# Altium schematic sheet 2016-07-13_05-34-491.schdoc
size 229 x 134 mm; SheetNumber: 1; SheetTotal: 1
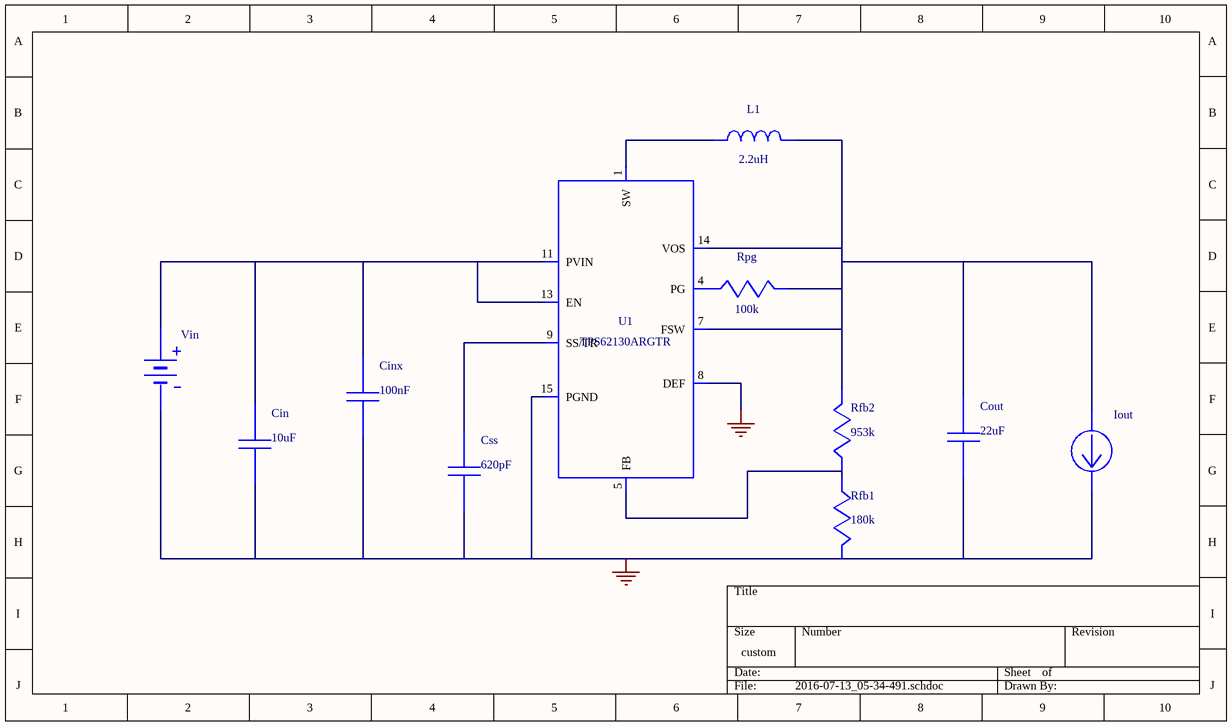
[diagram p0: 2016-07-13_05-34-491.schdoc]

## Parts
Cin  value 10uF  (hidden comment: TMK316BJ106KL-T)
Cinx  value 100nF  (hidden comment: C0603C104K3RACTU)
Cout  value 22uF  (hidden comment: GRM31CR61A226KE19L)
Css  value 620pF  (hidden comment: CL21C621JBCNNNC)
Iout  WB_CURRENT_LOAD  (value not drawn)
L1  value 2.2uH  (hidden comment: SRN8040-2R2Y)
Rfb1  value 180k  (hidden comment: RC0603FR-07180KL)
Rfb2  value 953k  (hidden comment: CRCW0402953KFKED)
Rpg  value 100k  (hidden comment: CRCW0402100KFKED)
U1  TPS62130ARGTR
Vin  WB_BATTERY  (value not drawn)

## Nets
0: Cin.2 Cinx.2 Cout.2 Css.2 Iout.2(-) Rfb1.1 U1.6(AGND) U1.8(DEF) U1.15(PGND) U1.16(PGND) U1.17(ETPAD) Vin.2(-)
NetCin_1: Cin.1 Cinx.1 U1.10(AVIN) U1.11(PVIN) U1.12(PVIN) U1.13(EN) Vin.1(+)
NetCout_1: Cout.1 Iout.1(+) L1.2 Rfb2.1 Rpg.1 U1.7(FSW) U1.14(VOS)
NetCss_1: Css.1 U1.9(SS/TR)
NetL1_1: L1.1 U1.1(SW) U1.2(SW) U1.3(SW)
NetRfb1_2: Rfb1.2 Rfb2.2 U1.5(FB)
NetRpg_2: Rpg.2 U1.4(PG)

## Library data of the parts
Cin = TMK316BJ106KL-T: Manufacturer Name: Taiyo Yuden
Cinx = C0603C104K3RACTU: Manufacturer Name: Kemet
Cout = GRM31CR61A226KE19L: GRM31CR61A226KE1; Manufacturer Name: MuRata
Css = CL21C621JBCNNNC: Manufacturer Name: Samsung Electro-Mechanics
L1 = SRN8040-2R2Y: Manufacturer Name: Bourns
Rfb1 = RC0603FR-07180KL: Manufacturer Name: Yageo America
Rfb2 = CRCW0402953KFKED: Manufacturer Name: Vishay-Dale
Rpg = CRCW0402100KFKED: Manufacturer Name: Vishay-Dale
U1 = TPS62130ARGTR: Manufacturer Name: Texas Instruments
